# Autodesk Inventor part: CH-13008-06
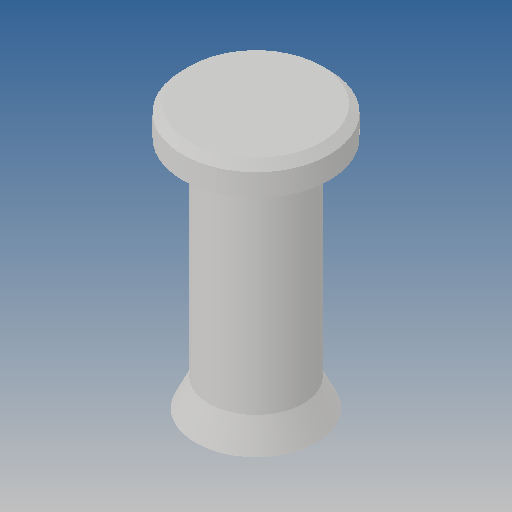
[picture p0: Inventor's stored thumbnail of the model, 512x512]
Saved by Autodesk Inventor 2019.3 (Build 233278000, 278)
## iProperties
Created: 2012-09
Part Number: CH-13008-06
Material: Ogólny
Document SubType Name: Modeling
Designer: CADENGINEERING4
Density: 1 g/cm^3
Appearance: Domyślna
Author: CADENGINEERING4
Revision Number: ÈÎºÎ
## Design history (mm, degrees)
feature "Ðý×ª1"
node "Bryła1"
